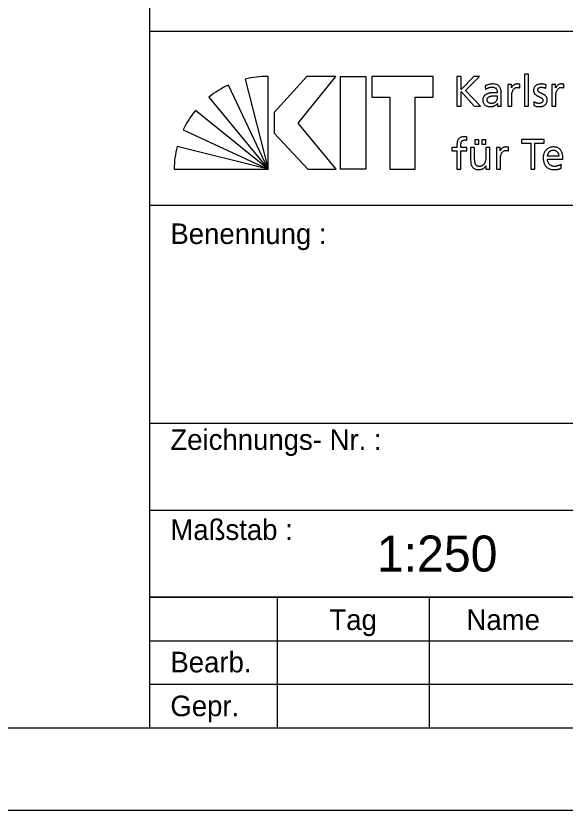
# Model space of a CAD drawing. Extents: x 0 to 105, y 0 to 74.
# Drawn here: x 78.75 to 92.08, y 0 to 19.29 of the extents above; entities that cross this region are included whole.
import ezdxf

# ---------------------------------------------------------------- set-up
doc = ezdxf.new("R2010")
doc.units = 0
doc.layers.add('90_Plankopf', color=7, linetype='Continuous')

msp = doc.modelspace()

# ---------------------------------------------------------------- linework, layer by layer
at = {"layer": '90_Plankopf'}
for p, q in [((82.001, 18.92), (82.001, 22.093)), ((82.001, 18.92), (103, 18.92)), ((84.319, 17.756), (84.87, 15.569)), ((84.87, 15.569), (84.87, 17.819)), ((89.453, 17.819), (89.453, 17.099)), ((84.87, 15.569), (83.909, 17.611)), ((90.145, 17.588), (90.15, 17.505)), ((90.982, 17.544), (90.982, 17.63)), ((91.614, 17.532), (91.623, 17.617)), ((92.053, 17.544), (92.053, 17.63)), ((90.53, 17.202), (90.53, 17.42)), ((83.436, 17.319), (84.87, 15.569)), ((90.433, 17.35), (90.433, 17.303)), ((91.325, 17.202), (91.319, 17.115)), ((84.87, 15.569), (83.109, 16.994)), ((89.453, 17.099), (89.556, 17.099)), ((89.877, 17.099), (90.027, 17.099)), ((82.81, 16.526), (84.87, 15.569)), ((89.694, 16.271), (89.698, 16.349)), ((84.87, 15.569), (82.665, 16.119)), ((90.707, 16.014), (90.707, 16.1)), ((91.927, 15.883), (91.654, 15.883)), ((91.654, 15.811), (92.03, 15.811)), ((91.99, 15.591), (91.99, 15.688)), ((82.591, 15.569), (84.87, 15.569)), ((82.001, 14.69), (103, 14.69)), ((82.001, 9.402), (103, 9.402)), ((82.001, 7.288), (103, 7.288)), ((82.001, 5.173), (103, 5.173)), ((82.001, 5.173), (103, 5.173)), ((82.001, 5.173), (103, 5.173)), ((82.001, 5.173), (103, 5.173)), ((82.001, 2), (82.001, 5.173)), ((85.089, 5.173), (85.089, 2)), ((88.794, 2), (88.794, 5.173)), ((82.001, 4.115), (92.5, 4.115)), ((82.001, 3.058), (92.5, 3.058)), ((82.001, 2), (103, 2)), ((82.001, 2), (103, 2))]:
    msp.add_line(p, q, dxfattribs=at)
for points in [[(0, 0), (105, 0), (105, 74.25), (0, 74.25)], [(2, 2), (103, 2), (103, 72.25), (2, 72.25)], [(86.517, 17.819), (85.809, 17.819), (85.018, 16.947), (85.018, 16.445), (85.835, 15.569), (86.521, 15.569), (85.606, 16.688)], [(87.243, 17.819), (87.243, 15.569), (86.626, 15.569), (86.626, 17.819)], [(87.391, 17.819), (87.391, 17.313), (87.826, 17.313), (87.826, 15.569), (88.443, 15.569), (88.443, 17.313), (88.878, 17.313), (88.878, 17.819)]]:
    msp.add_lwpolyline(points, close=True, dxfattribs=at)
for points in [[(82.001, 5.173), (82.001, 18.92)], [(90.027, 17.099), (89.662, 17.479), (90, 17.819), (89.863, 17.819), (89.556, 17.502), (89.556, 17.819), (89.453, 17.819)], [(91.095, 17.099), (91.192, 17.099), (91.192, 17.873), (91.095, 17.873), (91.095, 17.099)], [(90.781, 17.544), (90.779, 17.544), (90.779, 17.625), (90.688, 17.625), (90.688, 17.099), (90.785, 17.099), (90.785, 17.338)], [(91.852, 17.544), (91.85, 17.544), (91.85, 17.625), (91.759, 17.625), (91.759, 17.099), (91.856, 17.099), (91.856, 17.338)], [(89.556, 17.099), (89.556, 17.452), (89.877, 17.099)], [(90.441, 17.167), (90.443, 17.167), (90.443, 17.099), (90.534, 17.099)], [(89.889, 16.279), (89.889, 16.176), (89.986, 16.176), (89.986, 16.279), (89.889, 16.279)], [(90.058, 16.279), (90.058, 16.176), (90.155, 16.176), (90.155, 16.279), (90.058, 16.279)], [(91.248, 15.569), (91.351, 15.569), (91.351, 16.198), (91.575, 16.198), (91.575, 16.289), (91.024, 16.289), (91.024, 16.198), (91.248, 16.198), (91.248, 15.569)], [(89.456, 16.144), (89.456, 16.095), (89.333, 16.095), (89.333, 16.017), (89.456, 16.017), (89.456, 15.569), (89.553, 15.569), (89.553, 16.017), (89.693, 16.017), (89.693, 16.095), (89.553, 16.095), (89.553, 16.152)], [(89.886, 15.823), (89.886, 16.095), (89.789, 16.095), (89.789, 15.783)], [(90.254, 15.569), (90.254, 16.095), (90.157, 16.095), (90.157, 15.852)], [(90.506, 16.014), (90.504, 16.014), (90.504, 16.095), (90.413, 16.095), (90.413, 15.569), (90.51, 15.569), (90.51, 15.808)], [(90.158, 15.653), (90.16, 15.653), (90.16, 15.569), (90.254, 15.569)], [(103, 5.173), (82.001, 5.173)], [(82.001, 5.173), (82.001, 5.173)], [(82.001, 2), (103, 2)]]:
    msp.add_lwpolyline(points, dxfattribs=at)
for centre, start, end in [((84.862, 15.437), 89.8053, 103.1895), ((84.916, 15.452), 115.0126, 128.3968), ((84.954, 15.488), 140.7898, 154.174), ((84.973, 15.532), 165.7222, 179.1064)]:
    msp.add_arc(centre, 2.382, start, end, dxfattribs=at)
for points in [[(90.53, 17.42), (90.53, 17.468), (90.523, 17.508), (90.509, 17.54), (90.494, 17.572), (90.471, 17.597), (90.44, 17.613), (90.409, 17.629), (90.368, 17.637), (90.318, 17.637), (90.285, 17.637), (90.254, 17.633), (90.225, 17.624), (90.196, 17.615), (90.169, 17.603), (90.145, 17.588)], [(90.15, 17.505), (90.163, 17.516), (90.178, 17.526), (90.195, 17.534), (90.212, 17.542), (90.229, 17.548), (90.248, 17.553), (90.266, 17.557), (90.284, 17.559), (90.303, 17.559), (90.335, 17.559), (90.361, 17.554), (90.38, 17.544), (90.399, 17.533), (90.412, 17.518), (90.421, 17.498), (90.429, 17.477), (90.433, 17.452), (90.433, 17.422)], [(90.982, 17.63), (90.975, 17.632), (90.969, 17.633), (90.963, 17.634), (90.956, 17.635), (90.95, 17.636), (90.943, 17.636), (90.936, 17.637), (90.927, 17.637), (90.918, 17.637), (90.899, 17.637), (90.881, 17.633), (90.863, 17.625), (90.846, 17.617), (90.83, 17.606), (90.815, 17.592), (90.801, 17.578), (90.789, 17.562), (90.781, 17.544)], [(91.623, 17.617), (91.604, 17.623), (91.585, 17.628), (91.565, 17.631), (91.546, 17.635), (91.525, 17.637), (91.502, 17.637), (91.476, 17.637), (91.452, 17.634), (91.429, 17.628), (91.407, 17.621), (91.387, 17.611), (91.37, 17.598), (91.353, 17.584), (91.34, 17.567), (91.331, 17.547), (91.321, 17.527), (91.316, 17.503), (91.316, 17.476), (91.316, 17.455), (91.321, 17.436), (91.329, 17.421), (91.337, 17.406), (91.348, 17.392), (91.362, 17.381), (91.375, 17.37), (91.39, 17.36), (91.406, 17.351), (91.422, 17.343), (91.438, 17.334), (91.455, 17.327), (91.471, 17.319), (91.486, 17.311), (91.499, 17.303), (91.513, 17.295), (91.524, 17.286), (91.532, 17.276), (91.54, 17.266), (91.544, 17.254), (91.544, 17.24), (91.544, 17.226), (91.541, 17.214), (91.535, 17.205), (91.529, 17.195), (91.521, 17.187), (91.511, 17.181), (91.502, 17.175), (91.491, 17.171), (91.48, 17.169), (91.468, 17.166), (91.456, 17.165), (91.445, 17.165), (91.436, 17.165), (91.424, 17.166), (91.41, 17.169), (91.396, 17.172), (91.382, 17.176), (91.367, 17.182), (91.352, 17.187), (91.338, 17.194), (91.325, 17.202)], [(91.319, 17.115), (91.342, 17.104), (91.365, 17.096), (91.39, 17.092), (91.414, 17.088), (91.439, 17.086), (91.464, 17.087), (91.488, 17.087), (91.51, 17.09), (91.532, 17.096), (91.554, 17.103), (91.574, 17.113), (91.591, 17.126), (91.608, 17.14), (91.622, 17.157), (91.632, 17.178), (91.642, 17.198), (91.647, 17.223), (91.648, 17.251), (91.647, 17.275), (91.643, 17.295), (91.635, 17.311), (91.627, 17.328), (91.616, 17.342), (91.602, 17.354), (91.589, 17.366), (91.574, 17.375), (91.558, 17.384), (91.542, 17.392), (91.525, 17.4), (91.509, 17.407), (91.493, 17.414), (91.478, 17.421), (91.465, 17.429), (91.451, 17.437), (91.44, 17.446), (91.432, 17.457), (91.424, 17.467), (91.42, 17.48), (91.419, 17.495), (91.42, 17.51), (91.424, 17.522), (91.433, 17.531), (91.441, 17.541), (91.452, 17.548), (91.466, 17.552), (91.48, 17.557), (91.496, 17.559), (91.512, 17.559), (91.518, 17.559), (91.526, 17.558), (91.535, 17.557), (91.544, 17.555), (91.554, 17.553), (91.564, 17.551), (91.574, 17.548), (91.584, 17.545), (91.593, 17.542), (91.602, 17.539), (91.609, 17.536), (91.614, 17.532)], [(92.053, 17.63), (92.046, 17.632), (92.04, 17.633), (92.034, 17.634), (92.028, 17.635), (92.021, 17.636), (92.014, 17.636), (92.007, 17.637), (91.999, 17.637), (91.989, 17.637), (91.97, 17.637), (91.952, 17.633), (91.934, 17.625), (91.917, 17.617), (91.901, 17.606), (91.887, 17.592), (91.872, 17.578), (91.861, 17.562), (91.852, 17.544)], [(90.433, 17.422), (90.42, 17.423), (90.409, 17.423), (90.398, 17.423), (90.387, 17.424), (90.376, 17.424), (90.365, 17.424), (90.354, 17.424), (90.342, 17.424), (90.33, 17.424), (90.309, 17.424), (90.288, 17.422), (90.266, 17.419), (90.244, 17.415), (90.222, 17.409), (90.2, 17.401), (90.179, 17.393), (90.16, 17.382), (90.142, 17.369), (90.125, 17.355), (90.111, 17.339), (90.101, 17.319), (90.091, 17.3), (90.086, 17.277), (90.085, 17.251), (90.086, 17.213), (90.094, 17.181), (90.11, 17.157), (90.126, 17.133), (90.149, 17.115), (90.178, 17.104), (90.207, 17.092), (90.24, 17.087), (90.278, 17.087), (90.3, 17.087), (90.32, 17.089), (90.338, 17.095), (90.355, 17.1), (90.371, 17.107), (90.384, 17.115), (90.398, 17.123), (90.409, 17.132), (90.419, 17.141), (90.428, 17.15), (90.435, 17.159), (90.441, 17.167)], [(90.785, 17.338), (90.785, 17.383), (90.791, 17.421), (90.803, 17.453), (90.815, 17.485), (90.831, 17.509), (90.853, 17.527), (90.874, 17.544), (90.899, 17.553), (90.928, 17.553), (90.937, 17.553), (90.945, 17.552), (90.955, 17.551), (90.964, 17.55), (90.973, 17.547), (90.982, 17.544)], [(91.856, 17.338), (91.856, 17.383), (91.862, 17.421), (91.874, 17.453), (91.886, 17.485), (91.902, 17.509), (91.924, 17.527), (91.945, 17.544), (91.97, 17.553), (91.999, 17.553), (92.008, 17.553), (92.017, 17.552), (92.026, 17.551), (92.035, 17.55), (92.044, 17.547), (92.053, 17.544)], [(90.433, 17.303), (90.433, 17.277), (90.427, 17.253), (90.416, 17.233), (90.405, 17.212), (90.389, 17.195), (90.367, 17.183), (90.345, 17.171), (90.318, 17.165), (90.286, 17.165), (90.275, 17.165), (90.264, 17.167), (90.252, 17.17), (90.241, 17.174), (90.23, 17.18), (90.221, 17.187), (90.211, 17.194), (90.203, 17.203), (90.197, 17.214), (90.192, 17.224), (90.189, 17.237), (90.188, 17.251), (90.189, 17.269), (90.193, 17.285), (90.202, 17.297), (90.211, 17.309), (90.223, 17.319), (90.238, 17.326), (90.252, 17.334), (90.267, 17.339), (90.284, 17.343), (90.3, 17.347), (90.316, 17.349), (90.332, 17.35), (90.347, 17.351), (90.36, 17.352), (90.371, 17.352), (90.381, 17.352), (90.392, 17.351), (90.402, 17.351), (90.412, 17.35), (90.423, 17.35), (90.433, 17.35)], [(90.534, 17.099), (90.533, 17.104), (90.533, 17.111), (90.532, 17.119), (90.531, 17.128), (90.531, 17.139), (90.531, 17.152), (90.53, 17.166), (90.53, 17.182), (90.53, 17.202)], [(89.698, 16.349), (89.688, 16.351), (89.678, 16.352), (89.667, 16.353), (89.656, 16.355), (89.645, 16.355), (89.633, 16.355), (89.597, 16.355), (89.568, 16.35), (89.545, 16.34), (89.522, 16.33), (89.504, 16.316), (89.491, 16.297), (89.478, 16.279), (89.469, 16.257), (89.464, 16.231), (89.459, 16.205), (89.456, 16.176), (89.456, 16.144)], [(89.553, 16.152), (89.553, 16.17), (89.554, 16.186), (89.556, 16.202), (89.558, 16.217), (89.563, 16.23), (89.569, 16.241), (89.575, 16.252), (89.585, 16.261), (89.597, 16.267), (89.61, 16.274), (89.626, 16.277), (89.647, 16.277), (89.656, 16.277), (89.664, 16.276), (89.672, 16.275), (89.681, 16.274), (89.688, 16.273), (89.694, 16.271)], [(90.707, 16.1), (90.7, 16.102), (90.694, 16.103), (90.688, 16.104), (90.682, 16.105), (90.675, 16.106), (90.668, 16.107), (90.661, 16.107), (90.652, 16.108), (90.643, 16.108), (90.624, 16.107), (90.606, 16.103), (90.588, 16.095), (90.571, 16.088), (90.555, 16.077), (90.541, 16.062), (90.526, 16.048), (90.515, 16.032), (90.506, 16.014)], [(90.51, 15.808), (90.51, 15.853), (90.516, 15.891), (90.528, 15.923), (90.54, 15.955), (90.556, 15.98), (90.578, 15.997), (90.599, 16.014), (90.624, 16.023), (90.653, 16.023), (90.662, 16.023), (90.671, 16.023), (90.68, 16.021), (90.689, 16.02), (90.698, 16.017), (90.707, 16.014)], [(92.03, 15.811), (92.03, 15.853), (92.026, 15.892), (92.018, 15.928), (92.01, 15.964), (91.998, 15.996), (91.98, 16.023), (91.962, 16.049), (91.938, 16.07), (91.908, 16.085), (91.878, 16.1), (91.841, 16.107), (91.798, 16.108), (91.76, 16.107), (91.727, 16.101), (91.696, 16.088), (91.666, 16.075), (91.64, 16.057), (91.619, 16.033), (91.597, 16.009), (91.58, 15.981), (91.569, 15.949), (91.557, 15.916), (91.551, 15.881), (91.551, 15.841), (91.551, 15.798), (91.557, 15.76), (91.567, 15.725), (91.578, 15.69), (91.595, 15.66), (91.617, 15.635), (91.64, 15.61), (91.668, 15.591), (91.702, 15.577), (91.737, 15.564), (91.777, 15.557), (91.824, 15.557), (91.852, 15.557), (91.877, 15.559), (91.897, 15.563), (91.917, 15.566), (91.935, 15.571), (91.949, 15.576), (91.964, 15.581), (91.977, 15.586), (91.99, 15.591)], [(91.654, 15.883), (91.656, 15.9), (91.66, 15.917), (91.666, 15.934), (91.672, 15.951), (91.681, 15.967), (91.692, 15.982), (91.703, 15.996), (91.717, 16.007), (91.735, 16.016), (91.752, 16.025), (91.772, 16.029), (91.796, 16.029), (91.817, 16.029), (91.835, 16.025), (91.851, 16.018), (91.868, 16.01), (91.881, 16), (91.893, 15.986), (91.904, 15.973), (91.912, 15.957), (91.918, 15.94), (91.924, 15.922), (91.927, 15.903), (91.927, 15.883)], [(90.157, 15.852), (90.157, 15.82), (90.154, 15.79), (90.148, 15.764), (90.141, 15.737), (90.132, 15.715), (90.118, 15.695), (90.105, 15.676), (90.089, 15.661), (90.069, 15.651), (90.048, 15.64), (90.025, 15.635), (89.997, 15.635), (89.969, 15.637), (89.947, 15.645), (89.931, 15.659), (89.914, 15.673), (89.903, 15.694), (89.896, 15.721), (89.889, 15.748), (89.886, 15.782), (89.886, 15.823)], [(89.789, 15.783), (89.789, 15.735), (89.796, 15.695), (89.809, 15.661), (89.823, 15.628), (89.845, 15.602), (89.874, 15.584), (89.903, 15.566), (89.94, 15.557), (89.986, 15.557), (90.01, 15.557), (90.034, 15.561), (90.057, 15.568), (90.079, 15.576), (90.099, 15.587), (90.117, 15.601), (90.134, 15.616), (90.148, 15.633), (90.158, 15.653)], [(91.99, 15.688), (91.984, 15.683), (91.975, 15.677), (91.963, 15.671), (91.952, 15.665), (91.939, 15.66), (91.924, 15.654), (91.909, 15.649), (91.893, 15.644), (91.877, 15.641), (91.86, 15.637), (91.844, 15.635), (91.828, 15.635), (91.804, 15.635), (91.783, 15.639), (91.762, 15.648), (91.741, 15.656), (91.723, 15.668), (91.707, 15.684), (91.69, 15.699), (91.678, 15.718), (91.668, 15.739), (91.659, 15.761), (91.655, 15.784), (91.654, 15.811)]]:
    msp.add_open_spline(points, degree=3, dxfattribs=at)

# ---------------------------------------------------------------- texts
for s, height, p in [('Benennung :', 0.5, (82.5, 13.75)), ('Zeichnungs- Nr. :', 0.5, (82.5, 8.75)), ('Maßstab :', 0.5, (82.5, 6.562)), ('1:250   ', 0.875, (87.512, 5.794)), ('Tag', 0.5, (86.361, 4.375)), ('Name', 0.5, (89.688, 4.375)), ('Bearb.', 0.5, (82.5, 3.346)), ('Gepr.', 0.5, (82.5, 2.281))]:
    msp.add_text(s, height=height, dxfattribs=at).set_placement(p)

doc.saveas('drawing.dxf')
